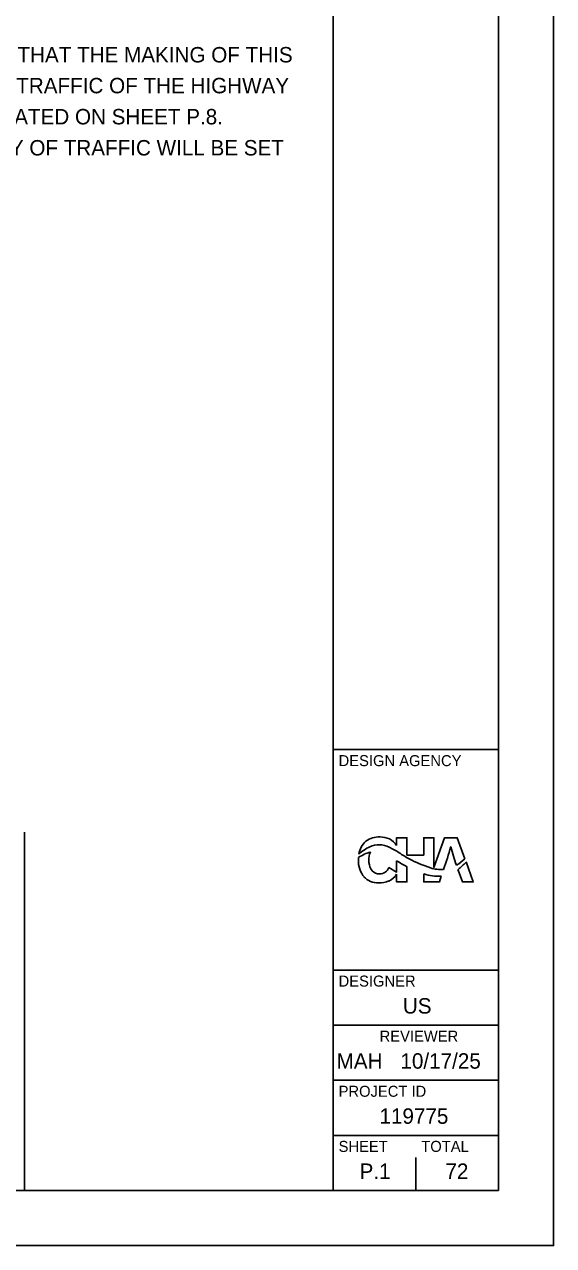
# Model space of a CAD drawing. Extents: x 0 to 44, y -23.8 to 22.
# Drawn here: x 29.2 to 34, y 0 to 11.08 of the extents above; entities that cross this region are included whole.
import ezdxf

# ---------------------------------------------------------------- set-up
doc = ezdxf.new("R2010")
doc.units = 0
for name, color, linetype in [('Default', 7, 'Continuous'), ('SH_Border', 7, 'Continuous'), ('SH_Cut_Line', 7, 'Continuous'), ('SH_Data', 7, 'Continuous'), ('SH_Text', 7, 'Continuous')]:
    doc.layers.add(name, color=color, linetype=linetype)

msp = doc.modelspace()

# ---------------------------------------------------------------- linework, layer by layer
at = {"layer": 'Default'}
msp.add_line((33.066, 3.619), (33.069, 3.619), dxfattribs=at)
for points in [[(33.196, 3.508), (33.126, 3.7), (33.012, 3.7), (32.915, 3.431), (32.915, 3.7), (32.822, 3.7), (32.822, 3.543), (32.669, 3.543), (32.669, 3.7), (32.576, 3.7), (32.576, 3.629)], [(32.576, 3.492), (32.576, 3.389), (32.507, 3.43)], [(32.576, 3.37), (32.576, 3.3), (32.669, 3.3), (32.669, 3.439)], [(33.133, 3.413), (33.144, 3.383), (33.173, 3.3), (33.272, 3.3), (33.206, 3.481)], [(32.822, 3.373), (32.822, 3.3), (32.867, 3.3), (32.915, 3.3), (32.964, 3.3), (32.981, 3.351)]]:
    msp.add_lwpolyline(points, dxfattribs=at)
for centre, radius, start, end in [((32.414, 3.529), 0.181, 129.6629, 172.5664), ((32.418, 3.503), 0.205, 88.0817, 126.0325), ((32.43, 3.514), 0.194, 64.9016, 91.2438), ((32.442, 3.551), 0.155, 30.3756, 63.3712), ((32.441, 3.209), 0.376, 105.7483, 123.9538), ((32.505, 3.249), 0.407, 114.8364, 131.7457), ((32.516, 3.499), 0.192, 157.8882, 204.8663), ((32.417, 3.436), 0.201, 63.1724, 114.4396), ((32.183, 2.916), 0.771, 57.2913, 65.1), ((33.592, 5.1), 1.829, 237.1308, 240.4227), ((31.298, 4.056), 1.821, 339.3263, 346.125), ((34.073, 3.831), 1.026, 191.9132, 201.6837), ((32.471, 3.495), 0.242, 173.6843, 214.2778), ((33.232, 4.512), 1.213, 237.2686, 242.3197), ((33.204, 4.445), 1.067, 241.1998, 252.5446), ((32.877, 3.865), 0.479, 300.42, 311.7894), ((32.822, 3.823), 0.515, 307.219, 318.2934), ((32.347, 3.41), 0.0923, 214.2778, 222.6269), ((32.407, 3.465), 0.174, 222.6269, 271.9347), ((32.404, 3.447), 0.0681, 204.8663, 223.055), ((32.418, 3.46), 0.0871, 223.055, 273.5972), ((32.424, 3.461), 0.0879, 269.2163, 339.4439), ((32.441, 3.453), 0.159, 294.1165, 328.289), ((32.953, 3.737), 0.386, 250.2087, 274.1935), ((32.979, 3.72), 0.308, 251.9229, 274.261), ((32.423, 3.511), 0.219, 267.5421, 292.3552)]:
    msp.add_arc(centre, radius, start, end, dxfattribs=at)
at = {"layer": 'SH_Border'}
for p, q in [((32, 0.5), (32, 21.5)), ((32, 4.5), (33.5, 4.5)), ((32, 2.5), (33.5, 2.5)), ((32, 2), (33.5, 2)), ((32, 1.5), (33.5, 1.5)), ((32, 1), (33.5, 1))]:
    msp.add_line(p, q, dxfattribs=at)
msp.add_lwpolyline([(1.5, 21.5), (33.5, 21.5), (33.5, 0.5), (1.5, 0.5)], close=True, dxfattribs=at)
at = {"layer": 'SH_Cut_Line'}
msp.add_lwpolyline([(0, 0), (34, 0), (34, 22), (0, 22)], close=True, dxfattribs=at)
at = {"layer": 'SH_Data'}
for p, q in [((32.75, 3.5), (32.75, 3.5)), ((32.75, 0.5), (32.75, 0.8)), ((32.375, 0.675), (32.375, 0.675))]:
    msp.add_line(p, q, dxfattribs=at)
at = {"layer": 'SH_Text'}
for p, q in [((29.2, 3.75), (29.2, 0.5)), ((32, 0.5), (32, 0.5))]:
    msp.add_line(p, q, dxfattribs=at)

# ---------------------------------------------------------------- texts
at = {"layer": 'Default'}
for s, p in [('I HEREBY APPROVE THESE PLANS AND DECLARE THAT THE MAKING OF THIS', (24.528, 10.735)), ('IMPROVEMENTS WILL REQUIRE THE CLOSING TO TRAFFIC OF THE HIGHWAY ', (24.528, 10.455)), ('AND THAT DETOURS WILL BE PROVIDED AS INDICATED ON SHEET P.8.', (24.52, 10.173)), ('PROVISIONS FOR THE MAINTENANCE AND SAFETY OF TRAFFIC WILL BE SET', (24.512, 9.891))]:
    msp.add_text(s, height=0.14, dxfattribs=at).set_placement(p)
at = {"layer": 'SH_Data'}
for s, height, p in [('DESIGN AGENCY', 0.1, (32.05, 4.35)), ('DESIGNER', 0.1, (32.05, 2.35)), ('US', 0.14, (32.633, 2.105)), ('REVIEWER', 0.1, (32.422, 1.85)), ('MAH', 0.14, (32.032, 1.605)), ('10/17/25', 0.14, (32.611, 1.605)), ('PROJECT ID', 0.1, (32.05, 1.35)), ('119775', 0.14, (32.421, 1.105)), ('SHEET', 0.1, (32.05, 0.85)), ('TOTAL', 0.1, (32.8, 0.85)), ('P.1', 0.14, (32.24, 0.605)), ('72', 0.14, (33.019, 0.605))]:
    msp.add_text(s, height=height, dxfattribs=at).set_placement(p)

doc.saveas('drawing.dxf')
